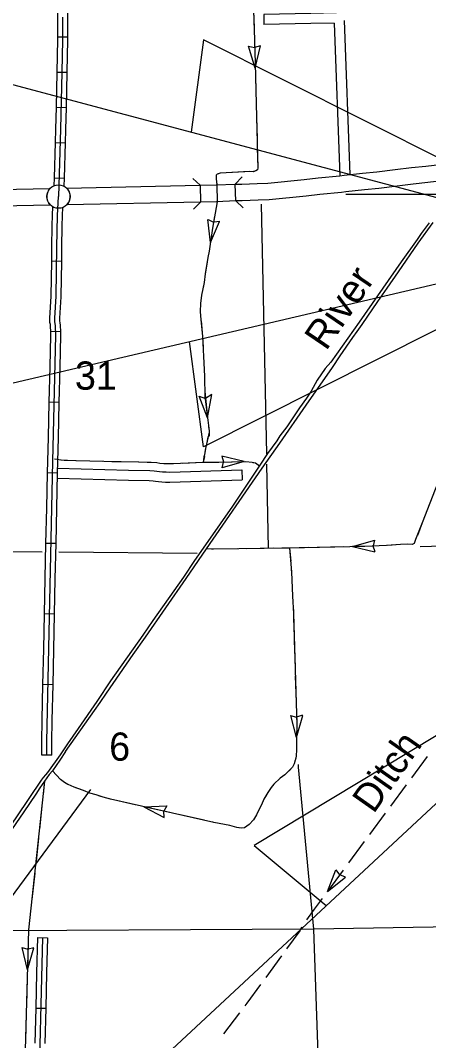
# Model space of a CAD drawing. Extents: x -5566 to 1759129, y -3726 to 731467.
# Drawn here: x -4880.9 to -4834.6, y 214.9 to 330.8 of the extents above; entities that cross this region are included whole.
import ezdxf

# ---------------------------------------------------------------- set-up
doc = ezdxf.new("R2010")
doc.units = 0
doc.layers.add('Default', color=7, linetype='Continuous')

msp = doc.modelspace()

# ---------------------------------------------------------------- linework, layer by layer
at = {"layer": 'Default'}
for p, q in [((-5045.08, 367.09), (-4814.18, 305.51)), ((-4876.73, 328.97), (-4875.59, 328.96)), ((-4854.29, 325.4), (-4855.03, 327.9)), ((-4855.03, 327.9), (-4854.36, 327.74)), ((-4853.68, 327.93), (-4854.35, 327.74)), ((-4854.29, 325.4), (-4853.68, 327.93)), ((-4876.78, 324.97), (-4875.64, 324.95)), ((-4876.87, 320.96), (-4875.73, 320.94)), ((-4876.97, 316.96), (-4875.84, 316.92)), ((-4877.1, 312.95), (-4875.96, 312.92)), ((-4859.36, 305.61), (-4859.65, 308.2)), ((-4859.63, 308.21), (-4859, 307.92)), ((-4859.36, 305.61), (-4858.32, 308)), ((-4858.3, 307.98), (-4858.99, 307.92)), ((-5037.98, 253.01), (-4814.18, 305.51)), ((-4876.23, 303.45), (-4877.37, 303.47)), ((-4876.34, 295.48), (-4877.48, 295.44)), ((-4876.51, 287.43), (-4877.65, 287.46)), ((-4860.64, 288.13), (-4859.93, 287.87)), ((-4859.7, 285.7), (-4860.64, 288.13)), ((-4859.21, 288.33), (-4859.93, 287.87)), ((-4859.7, 285.7), (-4859.21, 288.33)), ((-4855.53, 280.72), (-4858.06, 281.33)), ((-4858.06, 281.33), (-4857.87, 280.67)), ((-4855.53, 280.72), (-4858.03, 279.99)), ((-4858.03, 279.99), (-4857.87, 280.66)), ((-4876.71, 279.41), (-4877.85, 279.44)), ((-4876.88, 271.4), (-4878.02, 271.42)), ((-4843.22, 271.05), (-4840.72, 271.78)), ((-4840.73, 271.8), (-4840.88, 271.13)), ((-4843.22, 271.05), (-4840.69, 270.44)), ((-4840.67, 270.46), (-4840.88, 271.12)), ((-4877.05, 263.38), (-4878.19, 263.4)), ((-4877.22, 255.36), (-4878.36, 255.39)), ((-4850.27, 251.85), (-4849.6, 251.69)), ((-4849.58, 249.35), (-4850.23, 251.88)), ((-4848.92, 251.89), (-4849.59, 251.69)), ((-4849.58, 249.35), (-4848.88, 251.86)), ((-4877.36, 247.36), (-4878.5, 247.36)), ((-4866.91, 241.5), (-4864.31, 241.6)), ((-4866.91, 241.5), (-4864.6, 240.29)), ((-4864.31, 241.6), (-4864.63, 240.99)), ((-4864.6, 240.29), (-4864.63, 240.98)), ((-4846.09, 231.88), (-4845.13, 234.31)), ((-4845.13, 234.31), (-4844.7, 233.77)), ((-4846.09, 231.88), (-4844.05, 233.51)), ((-4844.05, 233.51), (-4844.69, 233.76)), ((-4878.99, 226.65), (-4877.85, 226.62)), ((-4880.13, 222.97), (-4880.73, 225.51)), ((-4880.73, 225.51), (-4880.07, 225.31)), ((-4880.13, 222.97), (-4879.38, 225.47)), ((-4879.38, 225.47), (-4880.06, 225.31)), ((-4879.19, 218.63), (-4878.05, 218.6))]:
    msp.add_line(p, q, dxfattribs=at)
for points in [[(-4856.17, 370.96), (-4855.94, 365.4), (-4855.76, 361.87), (-4855.53, 357.43), (-4855.39, 354.55), (-4855.39, 353.81), (-4855.4, 352.5), (-4855.27, 351.93), (-4855.29, 351.02), (-4855.25, 350.3), (-4855.15, 348.56), (-4855.04, 346.4), (-4854.85, 343.39), (-4854.76, 339.27), (-4854.69, 336.17), (-4854.45, 331.09), (-4854.3, 325.98), (-4854.12, 319.85)], [(-4876.67, 332.99), (-4876.71, 331.2), (-4876.73, 328.97)], [(-4875.53, 332.97), (-4875.57, 331.18), (-4875.59, 328.96)], [(-4854.51, 332.41), (-4854.45, 331.09), (-4854.4, 329.41)], [(-4845.06, 331.68), (-4847.98, 331.62), (-4853.31, 331.5), (-4853.29, 330.36)], [(-4876.14, 331.19), (-4876.16, 328.64), (-4876.21, 324.94), (-4876.36, 318.46), (-4876.6, 310.82)], [(-4845.32, 330.53), (-4847.96, 330.48), (-4853.29, 330.36)], [(-4845.32, 330.53), (-4844.68, 313.18)], [(-4844.19, 330.83), (-4843.55, 313.31)], [(-4876.73, 328.97), (-4876.73, 328.65), (-4876.78, 324.97)], [(-4875.59, 328.96), (-4875.59, 328.64), (-4875.64, 324.95)], [(-4814.18, 305.51), (-4814.18, 305.51), (-4860.15, 328.64), (-4861.56, 318.15)], [(-4854.37, 328.4), (-4854.3, 325.98), (-4854.29, 325.4)], [(-4876.78, 324.97), (-4876.78, 324.95), (-4876.87, 320.96)], [(-4875.64, 324.95), (-4875.64, 324.93), (-4875.73, 320.94)], [(-4854.26, 324.4), (-4854.21, 322.89)], [(-4854.21, 322.89), (-4854.17, 321.39)], [(-4876.87, 320.96), (-4876.93, 318.47), (-4876.97, 316.96)], [(-4875.73, 320.94), (-4875.79, 318.44), (-4875.84, 316.92)], [(-4854.14, 320.39), (-4854.12, 319.85), (-4854.06, 317.38)], [(-4854.12, 319.85), (-4853.98, 314.08), (-4854.02, 313.87), (-4854.2, 313.74), (-4854.52, 313.63), (-4854.91, 313.66), (-4858.27, 313.46), (-4858.59, 313.38), (-4858.71, 313.24), (-4858.7, 312.84), (-4858.62, 312.14), (-4858.6, 310.24)], [(-4876.97, 316.96), (-4877.1, 312.95)], [(-4875.84, 316.92), (-4875.96, 312.92)], [(-4854.04, 316.38), (-4853.98, 314.08), (-4854.02, 313.87), (-4854.2, 313.74), (-4854.46, 313.65)], [(-4856.54, 312.21), (-4855.81, 312.24), (-4854.04, 312.29), (-4852.83, 312.35), (-4848.71, 312.76), (-4847.15, 312.95), (-4844.68, 313.18), (-4844.18, 313.24), (-4842.09, 313.46), (-4840.46, 313.63), (-4838.39, 313.88), (-4836.55, 314.11), (-4834.9, 314.29), (-4832.68, 314.55), (-4832.46, 312.67)], [(-4877.1, 312.95), (-4877.13, 312.04)], [(-4855.46, 313.62), (-4858.27, 313.46), (-4858.45, 313.41)], [(-4856.54, 312.21), (-4855.77, 313.05)], [(-4875.96, 312.92), (-4875.99, 312)], [(-4875.65, 309.89), (-4875.53, 310.03), (-4875.4, 310.24), (-4875.3, 310.48), (-4875.26, 310.78), (-4875.28, 311.07), (-4875.37, 311.34), (-4875.51, 311.59), (-4875.69, 311.79), (-4860.54, 312.1), (-4860.5, 310.2)], [(-4861.36, 312.89), (-4860.54, 312.1)], [(-4860.54, 312.1), (-4858.72, 312.14), (-4856.54, 312.21)], [(-4858.67, 312.56), (-4858.62, 312.14)], [(-4832.46, 312.67), (-4834.69, 312.4), (-4836.34, 312.23), (-4838.16, 312), (-4840.25, 311.75), (-4841.89, 311.57), (-4843.98, 311.35), (-4844.49, 311.29), (-4846.95, 311.06), (-4848.51, 310.87), (-4852.69, 310.46), (-4853.96, 310.4), (-4855.75, 310.34), (-4856.48, 310.32), (-4856.54, 312.21)], [(-4890.96, 309.59), (-4891, 311.49), (-4877.55, 311.75), (-4877.72, 311.53), (-4877.86, 311.25), (-4877.92, 310.95), (-4877.92, 310.68), (-4877.87, 310.42), (-4877.72, 310.1), (-4877.51, 309.86)], [(-4877.93, 247.36), (-4877.93, 248.86), (-4877.25, 280.74), (-4876.89, 295.05), (-4876.93, 296.14), (-4876.96, 296.39), (-4877.02, 296.59), (-4877.01, 296.75), (-4877.02, 297.01), (-4876.85, 299.5), (-4876.79, 305.07), (-4876.71, 308.68), (-4876.6, 310.82)], [(-4844.01, 311.11), (-4833.22, 311.09)], [(-4877.51, 309.86), (-4890.96, 309.59)], [(-4877.31, 307.48), (-4877.28, 308.7), (-4877.23, 309.65)], [(-4876.17, 307.46), (-4876.14, 308.66), (-4876.09, 309.59)], [(-4860.5, 310.2), (-4875.65, 309.89)], [(-4860.5, 310.2), (-4861.29, 309.38)], [(-4858.6, 310.24), (-4859.11, 307.24), (-4859.5, 304.62), (-4859.64, 303.88), (-4859.95, 302.03), (-4860.08, 301.04), (-4860.37, 299.63), (-4860.49, 298.68), (-4860.54, 297.75), (-4860.44, 296.82), (-4860.25, 294.94), (-4860.04, 290.38), (-4860, 288.11), (-4859.67, 285.43), (-4859.5, 284.22), (-4859.52, 283.67), (-4859.67, 283.5), (-4859.82, 282.68), (-4859.91, 282.19), (-4860.04, 281.49), (-4860.09, 281.24), (-4860.2, 280.65)], [(-4856.48, 310.32), (-4858.67, 310.24), (-4860.5, 310.2)], [(-4858.6, 310.24), (-4858.71, 309.57)], [(-4855.65, 309.54), (-4856.48, 310.32)], [(-4853.6, 309.96), (-4853.01, 281.58)], [(-4858.88, 308.58), (-4859.11, 307.24), (-4859.36, 305.61)], [(-4877.37, 303.47), (-4877.36, 305.08), (-4877.31, 307.48)], [(-4834.53, 307.85), (-4835.45, 306.64), (-4835.91, 305.95), (-4837.71, 303.39), (-4842.48, 296.54), (-4845.7, 291.99), (-4846.33, 291.29), (-4847.26, 289.97), (-4847.93, 288.7), (-4848.47, 287.93), (-4849.26, 286.8), (-4850.7, 284.66), (-4851.47, 283.64), (-4851.83, 283.05), (-4852.89, 281.62), (-4853.76, 280.3), (-4856.87, 275.63), (-4859.65, 271.65), (-4861.16, 269.48), (-4862.43, 267.57), (-4863.53, 266.01), (-4865.89, 262.65), (-4867.02, 260.98), (-4870.71, 255.79), (-4872.26, 253.46), (-4874.36, 250.4), (-4875.58, 248.64), (-4876.4, 247.4)], [(-4876.23, 303.45), (-4876.22, 305.06), (-4876.17, 307.46)], [(-4875.8, 247.76), (-4872.53, 252.42), (-4871.89, 253.34), (-4871.16, 254.39), (-4868.14, 258.79), (-4866.71, 260.77), (-4862.13, 267.44), (-4859.81, 270.79), (-4853.48, 279.95), (-4851.49, 282.82), (-4848.5, 287.12), (-4845.52, 291.39), (-4844.65, 292.74), (-4843.2, 294.79), (-4842.7, 295.5), (-4842.14, 296.3), (-4840.37, 298.9), (-4839.32, 300.41), (-4838.01, 302.28), (-4835.8, 305.52), (-4834.07, 307.87)], [(-4814.18, 305.51), (-4860.15, 282.38), (-4861.75, 294.35)], [(-4859.5, 304.62), (-4859.5, 304.62), (-4859.64, 303.88), (-4859.76, 303.14)], [(-4877.42, 299.49), (-4877.42, 299.52), (-4877.37, 303.47)], [(-4876.28, 299.41), (-4876.28, 299.47), (-4876.23, 303.45)], [(-4859.76, 303.14), (-4859.95, 302.03), (-4860, 301.65)], [(-4860.16, 300.66), (-4860.37, 299.63), (-4860.49, 298.68), (-4860.54, 297.75), (-4860.53, 297.69)], [(-4877.48, 295.44), (-4877.5, 296.1), (-4877.52, 296.27), (-4877.6, 296.51), (-4877.58, 296.75), (-4877.59, 297.02), (-4877.42, 299.49)], [(-4876.34, 295.48), (-4876.36, 296.18), (-4876.4, 296.51), (-4876.45, 296.66), (-4876.44, 296.74), (-4876.45, 297), (-4876.28, 299.41)], [(-4860.42, 296.69), (-4860.25, 294.94), (-4860.19, 293.69)], [(-4877.55, 291.47), (-4877.46, 295.04), (-4877.48, 295.44)], [(-4876.41, 291.44), (-4876.32, 295.05), (-4876.34, 295.48)], [(-4860.15, 292.69), (-4860.04, 290.38), (-4860.03, 289.69)], [(-4877.65, 287.46), (-4877.55, 291.47)], [(-4876.51, 287.43), (-4876.41, 291.44)], [(-4860.01, 288.69), (-4859.7, 285.7)], [(-4877.75, 283.45), (-4877.65, 287.46)], [(-4876.61, 283.42), (-4876.51, 287.43)], [(-4859.57, 284.7), (-4859.5, 284.22), (-4859.5, 284.04), (-4859.82, 282.68), (-4859.91, 282.19), (-4859.99, 281.79)], [(-4877.85, 279.44), (-4877.82, 280.76), (-4877.75, 283.45)], [(-4876.71, 279.41), (-4876.68, 280.73), (-4876.61, 283.42)], [(-4877.05, 281.04), (-4876.75, 280.99), (-4876.35, 280.92), (-4875.96, 280.88), (-4874.65, 280.84), (-4871.46, 280.74), (-4867.49, 280.68), (-4866.07, 280.64), (-4865.43, 280.61), (-4865.1, 280.54), (-4864.64, 280.49), (-4863.62, 280.48), (-4860.2, 280.65), (-4858.39, 280.65), (-4855.33, 280.73), (-4854.64, 280.65), (-4854.26, 280.55), (-4853.79, 280.23)], [(-4876.23, 280.91), (-4875.96, 280.88), (-4875.56, 280.87)], [(-4874.56, 280.83), (-4871.55, 280.75)], [(-4870.55, 280.73), (-4867.54, 280.68)], [(-4866.54, 280.65), (-4866.07, 280.64), (-4865.43, 280.61), (-4865.1, 280.54), (-4864.64, 280.49), (-4863.62, 280.48), (-4863.55, 280.49)], [(-4862.54, 280.54), (-4860.2, 280.65), (-4859.54, 280.65)], [(-4860.05, 281.29), (-4860.2, 280.65)], [(-4858.54, 280.65), (-4858.39, 280.65), (-4855.53, 280.72)], [(-4854.54, 280.62), (-4854.26, 280.55), (-4853.79, 280.23)], [(-4877.93, 275.43), (-4877.85, 279.44)], [(-4876.79, 275.4), (-4876.71, 279.41)], [(-4876.7, 279.97), (-4868.64, 279.75), (-4866.24, 279.7), (-4865.73, 279.66), (-4865.44, 279.62), (-4865.12, 279.58), (-4864.78, 279.54), (-4864.4, 279.53), (-4863.95, 279.5), (-4855.78, 279.77), (-4855.74, 278.63)], [(-4832.97, 279.77), (-4835.34, 273.77), (-4836.07, 271.84), (-4836.24, 271.39), (-4836.46, 271.28), (-4837, 271.31), (-4837.78, 271.28), (-4839.37, 271.18), (-4841.83, 271.08), (-4850.37, 270.89), (-4859.02, 270.75), (-4859.81, 270.79)], [(-4852.99, 280.4), (-4852.79, 270.85)], [(-4876.72, 278.83), (-4868.67, 278.61), (-4866.3, 278.56), (-4865.86, 278.53), (-4865.6, 278.49), (-4865.25, 278.45), (-4864.86, 278.41), (-4864.46, 278.39), (-4863.97, 278.36), (-4855.74, 278.63)], [(-4878.02, 271.42), (-4877.93, 275.43)], [(-4876.88, 271.4), (-4876.79, 275.4)], [(-4834.8, 275.13), (-4835.34, 273.77), (-4835.88, 272.33)], [(-4878.1, 267.41), (-4878.02, 271.42)], [(-4876.97, 267.39), (-4876.88, 271.4)], [(-4836.24, 271.39), (-4836.24, 271.39), (-4836.46, 271.28), (-4837, 271.31), (-4837.78, 271.28), (-4839.21, 271.19)], [(-4835.56, 271.08), (-4813.44, 271.72)], [(-4891.43, 270.56), (-4878.46, 270.45)], [(-4876.58, 270.44), (-4860.88, 270.31)], [(-4856.25, 270.79), (-4859.02, 270.75), (-4859.25, 270.76)], [(-4852.24, 270.86), (-4855.24, 270.81)], [(-4848.23, 270.94), (-4850.37, 270.89), (-4851.24, 270.87)], [(-4850.37, 270.89), (-4850.16, 268.17), (-4850.03, 265.41), (-4849.94, 263.46), (-4849.57, 250.75), (-4849.59, 248.46), (-4849.59, 248.01)], [(-4850.37, 270.89), (-4850.25, 269.39)], [(-4845.72, 270.99), (-4847.23, 270.96)], [(-4844.22, 271.03), (-4845.72, 270.99)], [(-4840.21, 271.15), (-4841.83, 271.08), (-4843.22, 271.05)], [(-4850.18, 268.39), (-4850.16, 268.17), (-4850.03, 265.41), (-4850.03, 265.38)], [(-4878.19, 263.4), (-4878.1, 267.41)], [(-4877.05, 263.38), (-4876.97, 267.39)], [(-4849.98, 264.38), (-4849.94, 263.46), (-4849.88, 261.38)], [(-4956.37, 127.64), (-4956.37, 127.64), (-4810.33, 263.68)], [(-4878.28, 259.39), (-4878.19, 263.4)], [(-4877.14, 259.37), (-4877.05, 263.38)], [(-4810.33, 263.68), (-4854.4, 237.1), (-4846.23, 230.29)], [(-4849.85, 260.38), (-4849.76, 257.37)], [(-4878.36, 255.39), (-4878.28, 259.39)], [(-4877.22, 255.36), (-4877.14, 259.37)], [(-4849.73, 256.37), (-4849.64, 253.36)], [(-4878.45, 251.38), (-4878.36, 255.39)], [(-4877.31, 251.35), (-4877.22, 255.36)], [(-4849.61, 252.36), (-4849.57, 250.75), (-4849.58, 249.35)], [(-4878.5, 247.36), (-4878.5, 248.86), (-4878.45, 251.38)], [(-4877.36, 247.36), (-4877.36, 248.85), (-4877.31, 251.35)], [(-4849.59, 248.35), (-4849.59, 248.01), (-4849.64, 247.26), (-4849.72, 246.86)], [(-4876.4, 247.4), (-4877.86, 245.4), (-4878.09, 245.14), (-4878.34, 244.83), (-4878.58, 244.5), (-4881.37, 240.35), (-4884.41, 235.99), (-4885.86, 233.97), (-4890.88, 226.63), (-4895.17, 220.49), (-4898.6, 215.46), (-4912.27, 195.73), (-4915.76, 190.72), (-4920.35, 184.07), (-4921.09, 183.01), (-4923.05, 180.27), (-4923.53, 179.57), (-4923.92, 178.9)], [(-4875.8, 247.76), (-4876.46, 246.77), (-4877.29, 245.56), (-4877.64, 245.15), (-4878.17, 244.42), (-4878.72, 243.65), (-4879.18, 242.93), (-4880.54, 240.9), (-4885.6, 233.57), (-4890.03, 227.2), (-4895.07, 219.92), (-4898.37, 215.07), (-4906.21, 203.79), (-4910.67, 197.39), (-4914.14, 192.31), (-4916.83, 188.47), (-4918.42, 186.18), (-4919.9, 184.01), (-4922.4, 180.5), (-4923.48, 178.92)], [(-4849.59, 248.01), (-4849.64, 247.26), (-4849.73, 246.79), (-4849.84, 246.36), (-4850.03, 245.99), (-4850.9, 245.13), (-4851.45, 244.75), (-4852.18, 244.05), (-4852.46, 243.69), (-4852.85, 243.13), (-4853.3, 242.35), (-4853.56, 241.72), (-4853.82, 241.21), (-4854.13, 240.56), (-4854.48, 240.01), (-4854.97, 239.47), (-4855.49, 239.1), (-4855.82, 239.07), (-4856.35, 239.12), (-4857.14, 239.35), (-4858.96, 239.71), (-4870.69, 242.34), (-4871.54, 242.58), (-4872.34, 242.84), (-4873.04, 243.05), (-4873.78, 243.33), (-4874.82, 243.71), (-4875.5, 244.01), (-4875.93, 244.24), (-4876.36, 244.59), (-4877.29, 245.56)], [(-4834.78, 247.21), (-4836.56, 244.79)], [(-4849.72, 246.86), (-4849.73, 246.79), (-4849.84, 246.36), (-4850.03, 245.99), (-4850.44, 245.59)], [(-4847.62, 227.58), (-4849.37, 246), (-4849.38, 246.29)], [(-4875.55, 244.04), (-4875.93, 244.24), (-4876.36, 244.59), (-4877.29, 245.56)], [(-4851.19, 244.93), (-4851.45, 244.75), (-4852.18, 244.05), (-4852.46, 243.69), (-4852.85, 243.13), (-4853.12, 242.66)], [(-4872.96, 243.47), (-4888.59, 222.29), (-4888.9, 221.63), (-4894.9, 213.43), (-4903.43, 202.16), (-4913.29, 189.03), (-4916.78, 184.22), (-4917.39, 183.46), (-4918.39, 182.12), (-4918.72, 181.98), (-4918.91, 181.74), (-4919.08, 181.4), (-4919.19, 180.97), (-4920.21, 179.74), (-4920.86, 178.7), (-4922.02, 177.38), (-4935.68, 158.87), (-4947.25, 143.46), (-4948.57, 141.64), (-4960.58, 125.69), (-4969.88, 113.25)], [(-4878.17, 244.42), (-4880, 227.52), (-4880.39, 213.84), (-4880.65, 205.42), (-4880.87, 197.1), (-4880.71, 194.91), (-4880.74, 193.67), (-4880.8, 192.07), (-4880.84, 191.46), (-4880.86, 191.12), (-4880.95, 190.77)], [(-4878.17, 244.42), (-4878.33, 242.93)], [(-4871.78, 242.66), (-4872.34, 242.84), (-4873.04, 243.05), (-4873.78, 243.33), (-4874.63, 243.64)], [(-4837.16, 243.98), (-4838.94, 241.56)], [(-4869.36, 242.04), (-4870.69, 242.34), (-4870.82, 242.38)], [(-4878.44, 241.93), (-4878.76, 238.94)], [(-4867.89, 241.72), (-4869.36, 242.04)], [(-4863.98, 240.84), (-4866.91, 241.5)], [(-4853.55, 241.75), (-4853.56, 241.72), (-4853.82, 241.21), (-4854.13, 240.56), (-4854.48, 240.01), (-4854.97, 239.47), (-4855.21, 239.3)], [(-4860.06, 239.96), (-4863, 240.62)], [(-4839.54, 240.76), (-4841.32, 238.34)], [(-4856.15, 239.1), (-4856.35, 239.12), (-4857.14, 239.35), (-4858.96, 239.71), (-4859.09, 239.74)], [(-4878.87, 237.94), (-4879.19, 234.95)], [(-4841.92, 237.53), (-4843.7, 235.11)], [(-4844.3, 234.3), (-4846.09, 231.88)], [(-4879.3, 233.96), (-4879.62, 230.97)], [(-4846.68, 231.08), (-4847.57, 229.87)], [(-4879.73, 229.97), (-4880, 227.52), (-4880.01, 226.98)], [(-4847.57, 229.87), (-4848.47, 228.66)], [(-4847.62, 227.58), (-4889.68, 227.36)], [(-4849.02, 227.82), (-4849.23, 227.38), (-4850.72, 225.35)], [(-4809.32, 228.23), (-4847.62, 227.58)], [(-4846.42, 198.87), (-4846.93, 207.92), (-4847.62, 227.58)], [(-4878.42, 226.63), (-4878.92, 206.78), (-4879.1, 194.77), (-4879.13, 193.67), (-4879.12, 192.72), (-4879.14, 192.03), (-4879.23, 190.65), (-4879.32, 189.98), (-4879.47, 189.32), (-4879.57, 188.98), (-4879.77, 188.44), (-4879.95, 187.98), (-4880.03, 187.72), (-4880.06, 187.41), (-4880.11, 186.89)], [(-4878.99, 226.65), (-4879.09, 222.64)], [(-4877.85, 226.62), (-4877.95, 222.61)], [(-4880.04, 225.98), (-4880.13, 222.97)], [(-4851.31, 224.54), (-4853.08, 222.11)], [(-4879.09, 222.64), (-4879.19, 218.63)], [(-4877.95, 222.61), (-4878.05, 218.6)], [(-4880.16, 221.97), (-4880.2, 220.47)], [(-4880.2, 220.47), (-4880.24, 218.96)], [(-4853.68, 221.31), (-4855.23, 219.18), (-4855.46, 218.88)], [(-4880.27, 217.96), (-4880.36, 214.95)], [(-4879.19, 218.63), (-4879.29, 214.62)], [(-4878.05, 218.6), (-4878.15, 214.59)], [(-4856.06, 218.08), (-4857.88, 215.68)]]:
    msp.add_lwpolyline(points, dxfattribs=at)
msp.add_circle((-4876.6, 310.82), 1.33, dxfattribs=at)

# ---------------------------------------------------------------- texts
for s, rotation, p in [('River', 55.7334, (-4846.24, 293.2)), ('Ditch', 54.8397, (-4840.85, 240.6))]:
    msp.add_text(s, height=3.205, rotation=rotation, dxfattribs=at).set_placement(p)
for s, height, p in [('31', 3.205, (-4874.74, 288.88)), ('6', 3.2, (-4870.85, 246.73))]:
    msp.add_text(s, height=height, dxfattribs=at).set_placement(p)

doc.saveas('drawing.dxf')
